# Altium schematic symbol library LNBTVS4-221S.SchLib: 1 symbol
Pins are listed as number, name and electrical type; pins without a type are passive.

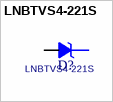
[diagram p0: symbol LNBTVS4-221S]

## LNBTVS4-221S
designator D?
footprint ST_SMC
pins: 1 K, 2 A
